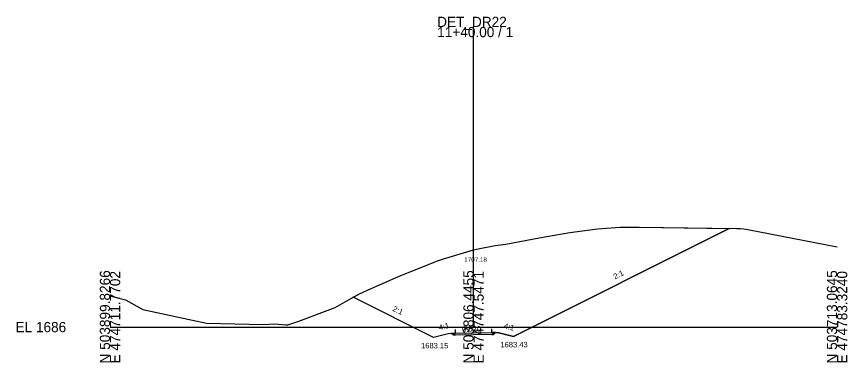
# Model space of a CAD drawing. Extents: x -26 to 1203, y -10 to 9633.
# Drawn here: x -25.7 to 202.8, y 3490.3 to 3585.3 of the extents above; entities that cross this region are included whole.
import ezdxf

# ---------------------------------------------------------------- set-up
doc = ezdxf.new("R2010")
doc.units = 0
for name, color, linetype in [('Exist Cross Section Cell', 7, 'Continuous'), ('Exist XS Center Line Elevation Label', 7, 'Continuous'), ('Exist XS Ground Line', 7, 'Continuous'), ('Prop XS Ditch Slope Text', 7, 'Continuous'), ('Prop XS Ditch Standard Text', 7, 'Continuous'), ('Prop XS Earthwork Shape', 7, 'Continuous'), ('Prop XS EOT Tick Mark', 7, 'Continuous'), ('Prop XS Finish Grade', 7, 'Continuous'), ('Prop XS Finish Grade Earthwork', 7, 'Continuous'), ('Prop XS Finish Grade Pavement', 7, 'Continuous'), ('Prop XS Pvmt Edge Slope', 7, 'Continuous'), ('Prop XS SE Text', 7, 'Continuous'), ('Prop XS Shoulder Borrow Shape', 7, 'Continuous'), ('Prop XS Side Slope Text', 7, 'Continuous'), ('Prop XS Subgrade Earthwork', 7, 'Continuous')]:
    doc.layers.add(name, color=color, linetype=linetype)

msp = doc.modelspace()

# ---------------------------------------------------------------- linework, layer by layer
at = {"layer": 'Exist Cross Section Cell'}
for p, q in [((100, 3500), (100, 3582.44)), ((0, 3500), (100, 3500)), ((100, 3500), (200, 3500))]:
    msp.add_line(p, q, dxfattribs=at)
at = {"layer": 'Exist XS Ground Line'}
msp.add_lwpolyline([(0, 3508.59), (2.38, 3507.97), (4.3, 3507.46), (8.99, 3504.79), (26.58, 3501.03), (42.11, 3500.74), (45.23, 3500.85), (48.37, 3500.62), (48.95, 3500.64), (51.91, 3501.64), (61.91, 3505.4), (65.82, 3507.56), (68.65, 3509.15), (71.83, 3510.57), (79.36, 3513.88), (89.19, 3517.86), (90.07, 3518.24), (91.49, 3518.67), (100, 3521.18), (100.79, 3521.41), (105.96, 3522.45), (108.88, 3522.76), (118.03, 3524.51), (126.52, 3525.94), (134.12, 3527.03), (140.37, 3527.46), (145.59, 3527.48), (172.34, 3527.05), (173.43, 3527.04), (174.33, 3526.96), (174.92, 3526.9), (175.45, 3526.82), (200, 3522.01)], dxfattribs=at)
at = {"layer": 'Prop XS Earthwork Shape'}
msp.add_lwpolyline([(145.59, 3527.48), (170.3, 3527.08), (111, 3497.43), (107, 3498.43), (106.02, 3498.47), (105.53, 3497.98), (105, 3497.97), (100, 3497.87), (95, 3497.77), (94.45, 3497.76), (93.98, 3498.23), (93, 3498.15), (89, 3497.15), (66.93, 3508.19), (68.65, 3509.15), (71.83, 3510.57), (79.36, 3513.88), (89.19, 3517.86), (90.07, 3518.24), (91.49, 3518.67), (100, 3521.18), (100.79, 3521.41), (105.96, 3522.45), (108.88, 3522.76), (118.03, 3524.51), (126.52, 3525.94), (134.12, 3527.03), (140.37, 3527.46)], close=True, dxfattribs=at)
at = {"layer": 'Prop XS EOT Tick Mark'}
for p, q in [((95, 3498.31), (95, 3499.31)), ((105, 3498.51), (105, 3499.51))]:
    msp.add_line(p, q, dxfattribs=at)
at = {"layer": 'Prop XS Finish Grade'}
for p, q in [((95, 3498.31), (93.98, 3498.23)), ((105, 3498.51), (106.02, 3498.47))]:
    msp.add_line(p, q, dxfattribs=at)
at = {"layer": 'Prop XS Finish Grade Earthwork'}
for p, q in [((111, 3497.43), (170.3, 3527.08)), ((89, 3497.15), (66.93, 3508.19)), ((93, 3498.15), (89, 3497.15)), ((93.98, 3498.23), (93, 3498.15)), ((106.02, 3498.47), (107, 3498.43)), ((107, 3498.43), (111, 3497.43))]:
    msp.add_line(p, q, dxfattribs=at)
at = {"layer": 'Prop XS Finish Grade Pavement'}
for p, q in [((95, 3498.31), (100, 3498.41)), ((100, 3498.41), (105, 3498.51))]:
    msp.add_line(p, q, dxfattribs=at)
at = {"layer": 'Prop XS Pvmt Edge Slope'}
for p, q in [((95, 3498.31), (94.45, 3497.76)), ((105, 3498.51), (105.53, 3497.98))]:
    msp.add_line(p, q, dxfattribs=at)
at = {"layer": 'Prop XS Shoulder Borrow Shape'}
for points in [[(95, 3498.31), (94.45, 3497.76), (93.98, 3498.23)], [(105.53, 3497.98), (106.02, 3498.47), (105, 3498.51)]]:
    msp.add_lwpolyline(points, close=True, dxfattribs=at)
at = {"layer": 'Prop XS Subgrade Earthwork'}
for p, q in [((94.45, 3497.76), (93.98, 3498.23)), ((95, 3497.77), (94.45, 3497.76)), ((100, 3497.87), (95, 3497.77)), ((105, 3497.97), (100, 3497.87)), ((105, 3497.97), (105.53, 3497.98)), ((105.53, 3497.98), (106.02, 3498.47))]:
    msp.add_line(p, q, dxfattribs=at)

# ---------------------------------------------------------------- texts
at = {"layer": 'Exist Cross Section Cell'}
for s, p in [('DET_DR22', (90, 3582.44)), ('11+40.00 / 1', (90, 3579.64)), ('EL 1686', (-26, 3498.6))]:
    msp.add_text(s, height=2.8, dxfattribs=at).set_placement(p)
for s, p in [('N 503899.8266', (0, 3490)), ('E 474711.7702', (2.8, 3490)), ('N 503806.4455', (100, 3490)), ('E 474747.5471', (102.8, 3490)), ('N 503713.0645', (200, 3490)), ('E 474783.3240', (202.8, 3490))]:
    msp.add_text(s, height=2.8, rotation=90, dxfattribs=at).set_placement(p)
at = {"layer": 'Exist XS Center Line Elevation Label'}
msp.add_text('1707.18', height=1.25, dxfattribs=at).set_placement((97.44, 3517.93))
at = {"layer": 'Prop XS Ditch Slope Text'}
for rotation, p in [(14.0362, (90.64, 3499.11)), (345.9638, (108.21, 3499.67))]:
    msp.add_text('4:1', height=1.5, rotation=rotation, dxfattribs=at).set_placement(p)
at = {"layer": 'Prop XS Ditch Standard Text'}
for s, p in [('1683.15', (85.57, 3494.15)), ('1683.43', (107.4, 3494.43))]:
    msp.add_text(s, height=1.5, dxfattribs=at).set_placement(p)
at = {"layer": 'Prop XS SE Text'}
msp.add_text('0.020', height=1.5, rotation=1.1458, dxfattribs=at).set_placement((96.85, 3498.67))
at = {"layer": 'Prop XS Side Slope Text'}
for rotation, p in [(26.5651, (138.92, 3513.07)), (333.4349, (77.57, 3504.54))]:
    msp.add_text('2:1', height=1.5, rotation=rotation, dxfattribs=at).set_placement(p)

doc.saveas('drawing.dxf')
